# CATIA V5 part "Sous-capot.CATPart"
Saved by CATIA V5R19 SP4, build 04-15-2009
Part number: Sous-capot
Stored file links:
  C:\Users\Marie\Documents\IFMA\2A\S1\CFAO\brevet_Sauret\Sous-capot.CATPart
  C:\Users\Marie\Documents\IFMA\2A\S1\CFAO\brevet_Sauret\Product3.CATProduct
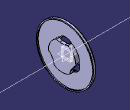
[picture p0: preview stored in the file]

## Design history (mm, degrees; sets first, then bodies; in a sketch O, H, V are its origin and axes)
Set1
  Plane1: linked copy from another document
  Line1: linked copy from another document
  Plane2: linked copy from another document
  Plane3: linked copy from another document
Body1 (main body)
  Sketch1 on Plane1, origin (0, 0, 0), H (1, 0, 0), V (0, 1, 0)
    line L1 (-4, 0) -> (-4, -110)
    line L2 (-4, -110) -> (0, -110)
    point P3 (0, -110)
    line L3 (0, -110) -> (0, -114)
    line L4 (0, -114) -> (8, -114)
    line L5 (8, -114) -> (8, -110)
    line L6 (8, -110) -> (4, -110)
    line L7 (4, -110) -> (4, 0)
    line L8 (4, 0) -> (-4, 0)
    vertical: L1 V, L3 V, L5 V, L7 V
    coincidence: P3 V
    horizontal: L2 H, L4 H, L6 H, L8 H
  Shaft1: profile Sketch1, axis Line1, angle 360
  Sketch2 on Plane2, origin (4, 0, 0), H (0, 1, 0), V (0, 0, 1)
    circle A1 centre (0, 0) radius 54
  Pad1: profile Sketch2, direction (1, 0, 0), length 15
  Sketch3 on Plane3, origin (-4, 0, 0), H (0, 1, 0), V (0, 0, 1)
    line L1 (22.953, 49.3177) -> (10, 44.9997)
    line L2 (10, 44.9997) -> (-10, 44.9997)
    line L3 (-10, 44.9997) -> (-22.953, 49.3177)
    arc A1 centre (0, 30) radius 30 from (22.9527, 49.3177) to (-22.9527, 49.3176) ccw
    point P5 (0, 30)
    point P6 (-22.9527, 49.3176)
    horizontal: L2 H
    coincidence: P5 V, L3 P6
  Pocket1: profile Sketch3, direction (-1, 0, 0), through (limit type 3)
  CircPattern1: of Pocket1, instances 3, angular step 120, axis from Line1
  Sketch4 on Plane3, origin (-4, 0, 0), H (0, 1, 0), V (0, 0, 1)
    circle A1 centre (0, 0) radius 52
  Pocket2: profile Sketch4, direction (1, 0, 0), length 12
